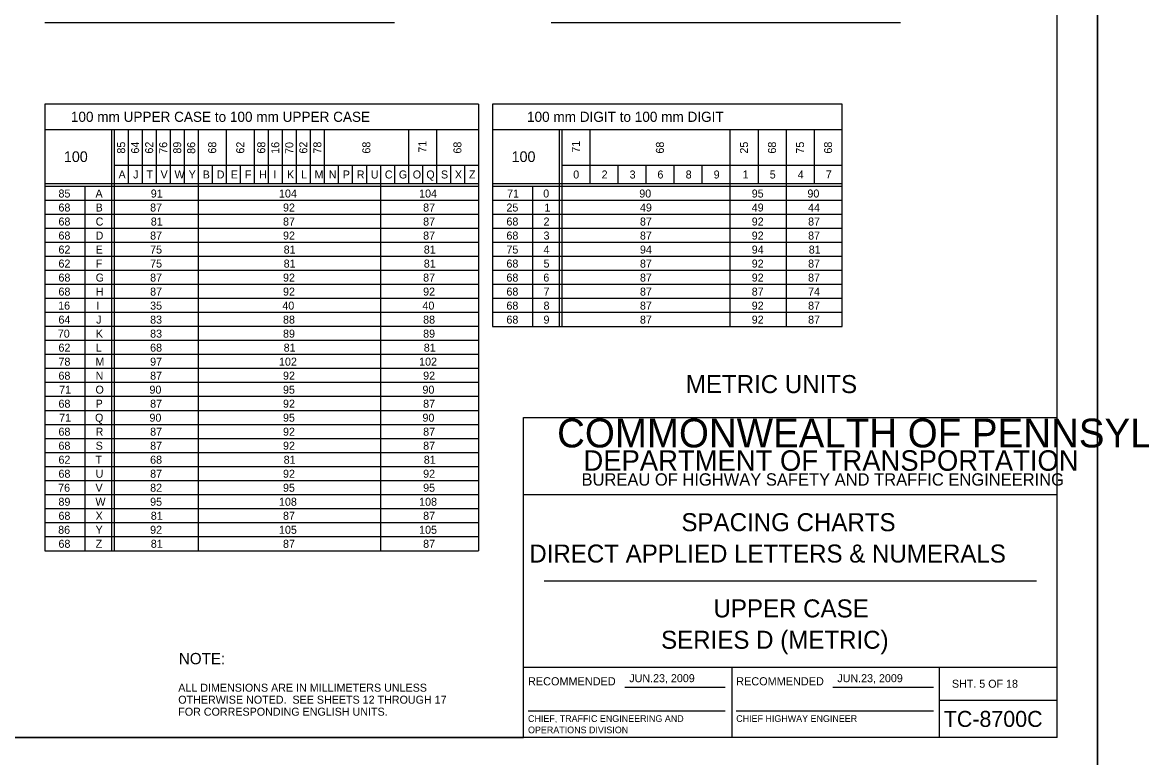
# Model space of a CAD drawing. Extents: x 637580 to 641849, y 297270 to 299646.
# Drawn here: x 638859.5 to 639278.9, y 299059.1 to 299334.6 of the extents above; entities that cross this region are included whole.
import ezdxf

# ---------------------------------------------------------------- set-up
doc = ezdxf.new("R2010")
doc.units = 0
for name, color, linetype in [('1', 7, 'Continuous'), ('2', 7, 'Continuous'), ('XCS-GRID-HVGL', 7, 'Continuous')]:
    doc.layers.add(name, color=color, linetype=linetype)

msp = doc.modelspace()

# ---------------------------------------------------------------- linework, layer by layer
at = {"layer": '1'}
for p, q in [((639247.31, 299066.63), (639247.31, 299630.63)), ((639047.31, 299066.63), (639047.31, 299186.63)), ((639047.31, 299186.63), (639247.31, 299186.63)), ((639247.31, 299157.63), (639047.31, 299157.63)), ((639055.06, 299125.31), (639239.56, 299125.31)), ((639047.31, 299093), (639247.31, 299093)), ((639125.31, 299093), (639125.31, 299066.63)), ((639203.19, 299066.63), (639203.19, 299093)), ((639085.24, 299085.57), (639122.87, 299085.57)), ((639163.24, 299085.57), (639200.87, 299085.57)), ((639048.99, 299076.68), (639122.87, 299076.68)), ((639126.99, 299076.68), (639200.87, 299076.68)), ((639203.19, 299080.63), (639247.31, 299080.63)), ((639247.31, 299066.63), (638461.31, 299066.63)), ((638461.31, 299066.63), (639047.31, 299066.63))]:
    msp.add_line(p, q, dxfattribs=at)
at = {"layer": '2'}
for p, q in [((638867.91, 299334.63), (638998.91, 299334.63)), ((639057.61, 299334.63), (639188.61, 299334.63)), ((639030.41, 299304), (638867.91, 299304)), ((638867.91, 299304), (638867.91, 299136.63)), ((639030.41, 299304), (639030.41, 299136.63)), ((639166.66, 299304), (639035.66, 299304)), ((639035.66, 299304), (639035.66, 299220.63)), ((639166.66, 299220.63), (639166.66, 299304)), ((638867.91, 299294.5), (639030.41, 299294.5)), ((638892.91, 299294.5), (638892.91, 299136.63)), ((638893.91, 299294.5), (638893.91, 299136.63)), ((638899.16, 299294.5), (638899.16, 299274.13)), ((638904.41, 299294.5), (638904.41, 299274.13)), ((638909.66, 299294.5), (638909.66, 299274.13)), ((638914.91, 299294.5), (638914.91, 299274.13)), ((638920.16, 299294.5), (638920.16, 299274.13)), ((638925.41, 299294.5), (638925.41, 299136.63)), ((638935.91, 299294.5), (638935.91, 299274.13)), ((638946.41, 299294.5), (638946.41, 299274.13)), ((638951.66, 299294.5), (638951.66, 299274.13)), ((638956.91, 299294.5), (638956.91, 299274.13)), ((638962.16, 299294.5), (638962.16, 299274.13)), ((638967.41, 299294.5), (638967.41, 299274.13)), ((638972.66, 299294.5), (638972.66, 299274.13)), ((639004.16, 299294.5), (639004.16, 299274.13)), ((639014.66, 299294.5), (639014.66, 299274.13)), ((639035.66, 299294.5), (639166.66, 299294.5)), ((639060.66, 299294.5), (639060.66, 299220.63)), ((639061.66, 299294.5), (639061.66, 299220.63)), ((639072.16, 299294.5), (639072.16, 299274.13)), ((639124.66, 299294.5), (639124.66, 299220.63)), ((639135.16, 299294.5), (639135.16, 299274.13)), ((639145.66, 299294.5), (639145.66, 299220.63)), ((639156.16, 299294.5), (639156.16, 299274.13)), ((638893.91, 299281.13), (639030.41, 299281.13)), ((638930.66, 299281.13), (638930.66, 299274.13)), ((638941.16, 299281.13), (638941.16, 299274.13)), ((638977.91, 299281.13), (638977.91, 299274.13)), ((638983.16, 299281.13), (638983.16, 299274.13)), ((638988.41, 299281.13), (638988.41, 299274.13)), ((638988.41, 299281.13), (638988.41, 299274.13)), ((638993.66, 299281.13), (638993.66, 299136.63)), ((638998.91, 299281.13), (638998.91, 299274.13)), ((639009.41, 299281.13), (639009.41, 299274.13)), ((639019.91, 299281.13), (639019.91, 299274.13)), ((639025.16, 299281.13), (639025.16, 299274.13)), ((639061.66, 299281.13), (639166.66, 299281.13)), ((639082.66, 299281.13), (639082.66, 299274.13)), ((639093.16, 299281.13), (639093.16, 299274.13)), ((639103.66, 299281.13), (639103.66, 299274.13)), ((639114.16, 299281.13), (639114.16, 299274.13)), ((639030.41, 299274.13), (638867.91, 299274.13)), ((639166.66, 299274.13), (639035.66, 299274.13)), ((639030.41, 299273.13), (638867.91, 299273.13)), ((638882.91, 299273.13), (638882.91, 299136.63)), ((639166.66, 299273.13), (639035.66, 299273.13)), ((639050.66, 299273.13), (639050.66, 299220.63)), ((639030.41, 299267.88), (638867.91, 299267.88)), ((639166.66, 299267.88), (639035.66, 299267.88)), ((639030.41, 299262.63), (638867.91, 299262.63)), ((639166.66, 299262.63), (639035.66, 299262.63)), ((639030.41, 299257.38), (638867.91, 299257.38)), ((639166.66, 299257.38), (639035.66, 299257.38)), ((639030.41, 299252.13), (638867.91, 299252.13)), ((639166.66, 299252.13), (639035.66, 299252.13)), ((639030.41, 299246.88), (638867.91, 299246.88)), ((639166.66, 299246.88), (639035.66, 299246.88)), ((639030.41, 299241.63), (638867.91, 299241.63)), ((639166.66, 299241.63), (639035.66, 299241.63)), ((639030.41, 299236.38), (638867.91, 299236.38)), ((639166.66, 299236.38), (639035.66, 299236.38)), ((639030.41, 299231.13), (638867.91, 299231.13)), ((639166.66, 299231.13), (639035.66, 299231.13)), ((639030.41, 299225.88), (638867.91, 299225.88)), ((639166.66, 299225.88), (639035.66, 299225.88)), ((639030.41, 299220.63), (638867.91, 299220.63)), ((639035.66, 299220.63), (639166.66, 299220.63)), ((639030.41, 299215.38), (638867.91, 299215.38)), ((639030.41, 299210.13), (638867.91, 299210.13)), ((639030.41, 299204.88), (638867.91, 299204.88)), ((639030.41, 299199.63), (638867.91, 299199.63)), ((639030.41, 299194.38), (638867.91, 299194.38)), ((639030.41, 299189.13), (638867.91, 299189.13)), ((639030.41, 299183.88), (638867.91, 299183.88)), ((639030.41, 299178.63), (638867.91, 299178.63)), ((639030.41, 299173.38), (638867.91, 299173.38)), ((639030.41, 299168.13), (638867.91, 299168.13)), ((639030.41, 299162.88), (638867.91, 299162.88)), ((639030.41, 299157.63), (638867.91, 299157.63)), ((639030.41, 299152.38), (638867.91, 299152.38)), ((639030.41, 299147.13), (638867.91, 299147.13)), ((639030.41, 299141.88), (638867.91, 299141.88)), ((638867.91, 299136.63), (638867.91, 299136.63)), ((638867.91, 299136.63), (639030.41, 299136.63))]:
    msp.add_line(p, q, dxfattribs=at)
at = {"layer": 'XCS-GRID-HVGL'}
for points in [[(638421.31, 299645.63), (639262.31, 299645.63), (639262.31, 299051.63), (638421.31, 299051.63)], [(639262.31, 299645.63), (640103.31, 299645.63), (640103.31, 299051.63), (639262.31, 299051.63)]]:
    msp.add_lwpolyline(points, close=True, dxfattribs=at)

# ---------------------------------------------------------------- texts
at = {"layer": '1'}
for s, height, p in [('COMMONWEALTH OF PENNSYLVANIA', 10.7828, (639059.9, 299175.36)), ('DEPARTMENT OF TRANSPORTATION', 7.6837, (639069.76, 299166.61)), ('BUREAU OF HIGHWAY SAFETY AND TRAFFIC ENGINEERING', 4.6253, (639069.04, 299161.04)), ('SPACING CHARTS', 6.75, (639106.47, 299143.97)), ('DIRECT APPLIED LETTERS & NUMERALS', 6.75, (639049.47, 299132.22)), ('UPPER CASE', 6.75, (639118.47, 299111.66)), ('SERIES D (METRIC)', 6.75, (639098.84, 299099.91)), ('RECOMMENDED', 3.048, (639048.99, 299086.2)), ('RECOMMENDED', 3.048, (639126.99, 299086.2)), ('SHT. 5 OF 18', 3, (639207.82, 299085.31)), ('TC-8700C', 6, (639204.77, 299070.63)), ('CHIEF, TRAFFIC ENGINEERING AND', 2.5, (639048.99, 299072.51)), ('CHIEF HIGHWAY ENGINEER', 2.5, (639126.99, 299072.51)), ('OPERATIONS DIVISION', 2.5, (639048.99, 299068.26))]:
    msp.add_text(s, height=height, dxfattribs=at).set_placement(p)
at = {"layer": '2'}
for s, height, p in [('100 mm UPPER CASE to 100 mm UPPER CASE', 3.8, (638877.7, 299297.35)), ('100 mm DIGIT to 100 mm DIGIT', 3.8, (639048.61, 299297.35)), ('100', 4, (638875.1, 299282.31)), ('100', 4, (639042.85, 299282.31)), ('A', 3, (638895.56, 299276.13)), ('J', 3, (638901.04, 299276.13)), ('T', 3, (638906.04, 299276.13)), ('V', 3, (638911.31, 299276.13)), ('W', 3, (638916.53, 299276.13)), ('Y', 3, (638921.84, 299276.13)), ('B', 3, (638927.1, 299276.13)), ('D', 3, (638932.35, 299276.13)), ('E', 3, (638937.62, 299276.13)), ('F', 3, (638942.92, 299276.13)), ('H', 3, (638948.19, 299276.13)), ('I', 3, (638953.6, 299276.13)), ('K', 3, (638958.69, 299276.13)), ('L', 3, (638963.94, 299276.13)), ('M', 3, (638969.03, 299276.13)), ('N', 3, (638974.35, 299276.13)), ('P', 3, (638979.6, 299276.13)), ('R', 3, (638984.85, 299276.13)), ('U', 3, (638990.09, 299276.13)), ('C', 3, (638995.35, 299276.13)), ('G', 3, (639000.6, 299276.13)), ('O', 3, (639005.81, 299276.13)), ('Q', 3, (639010.88, 299276.13)), ('S', 3, (639016.37, 299276.13)), ('X', 3, (639021.59, 299276.13)), ('Z', 3, (639026.85, 299276.13)), ('0', 3, (639065.93, 299276.13)), ('2', 3, (639076.56, 299276.13)), ('3', 3, (639087.06, 299276.13)), ('6', 3, (639097.48, 299276.13)), ('8', 3, (639108.06, 299276.13)), ('9', 3, (639118.55, 299276.13)), ('1', 3, (639129.4, 299276.13)), ('5', 3, (639139.56, 299276.13)), ('4', 3, (639150.06, 299276.13)), ('7', 3, (639160.56, 299276.13)), ('85', 3, (638873.06, 299269)), ('A', 3, (638886.93, 299269)), ('91', 3, (638907.65, 299269)), ('104', 3, (638955.69, 299269)), ('104', 3, (639008.19, 299269)), ('71', 3, (639041.15, 299269)), ('0', 3, (639054.68, 299269)), ('90', 3, (639090.68, 299269)), ('95', 3, (639132.81, 299269)), ('90', 3, (639153.68, 299269)), ('68', 3, (638873.06, 299263.75)), ('B', 3, (638886.98, 299263.75)), ('87', 3, (638907.4, 299263.75)), ('92', 3, (638957.19, 299263.75)), ('87', 3, (639009.69, 299263.75)), ('25', 3, (639040.9, 299263.75)), ('1', 3, (639055.15, 299263.75)), ('49', 3, (639090.93, 299263.75)), ('49', 3, (639132.81, 299263.75)), ('44', 3, (639153.93, 299263.75)), ('68', 3, (638873.06, 299258.5)), ('C', 3, (638886.98, 299258.5)), ('81', 3, (638907.65, 299258.5)), ('87', 3, (638957.19, 299258.5)), ('87', 3, (639009.69, 299258.5)), ('68', 3, (639040.9, 299258.5)), ('2', 3, (639054.81, 299258.5)), ('87', 3, (639090.93, 299258.5)), ('92', 3, (639132.81, 299258.5)), ('87', 3, (639153.93, 299258.5)), ('68', 3, (638873.06, 299253.25)), ('D', 3, (638886.98, 299253.25)), ('87', 3, (638907.4, 299253.25)), ('92', 3, (638957.19, 299253.25)), ('87', 3, (639009.69, 299253.25)), ('68', 3, (639040.9, 299253.25)), ('3', 3, (639054.81, 299253.25)), ('87', 3, (639090.93, 299253.25)), ('92', 3, (639132.81, 299253.25)), ('87', 3, (639153.93, 299253.25)), ('62', 3, (638873.06, 299248)), ('E', 3, (638886.99, 299248)), ('75', 3, (638907.4, 299248)), ('81', 3, (638957.44, 299248)), ('81', 3, (639009.94, 299248)), ('75', 3, (639040.9, 299248)), ('4', 3, (639054.81, 299248)), ('94', 3, (639090.93, 299248)), ('94', 3, (639132.81, 299248)), ('81', 3, (639154.18, 299248)), ('62', 3, (638873.06, 299242.75)), ('F', 3, (638887.05, 299242.75)), ('75', 3, (638907.4, 299242.75)), ('81', 3, (638957.44, 299242.75)), ('81', 3, (639009.94, 299242.75)), ('68', 3, (639040.9, 299242.75)), ('5', 3, (639054.81, 299242.75)), ('87', 3, (639090.93, 299242.75)), ('92', 3, (639132.81, 299242.75)), ('87', 3, (639153.93, 299242.75)), ('68', 3, (638873.06, 299237.5)), ('G', 3, (638886.98, 299237.5)), ('87', 3, (638907.4, 299237.5)), ('92', 3, (638957.19, 299237.5)), ('87', 3, (639009.69, 299237.5)), ('68', 3, (639040.9, 299237.5)), ('6', 3, (639054.73, 299237.5)), ('87', 3, (639090.93, 299237.5)), ('92', 3, (639132.81, 299237.5)), ('87', 3, (639153.93, 299237.5)), ('68', 3, (638873.06, 299232.25)), ('H', 3, (638887.06, 299232.25)), ('87', 3, (638907.4, 299232.25)), ('92', 3, (638957.19, 299232.25)), ('92', 3, (639009.69, 299232.25)), ('68', 3, (639040.9, 299232.25)), ('7', 3, (639054.81, 299232.25)), ('87', 3, (639090.93, 299232.25)), ('87', 3, (639132.81, 299232.25)), ('74', 3, (639153.93, 299232.25)), ('16', 3, (638872.94, 299227)), ('I', 3, (638887.23, 299227)), ('35', 3, (638907.4, 299227)), ('40', 3, (638956.94, 299227)), ('40', 3, (639009.44, 299227)), ('68', 3, (639040.9, 299227)), ('8', 3, (639054.81, 299227)), ('87', 3, (639090.93, 299227)), ('92', 3, (639132.81, 299227)), ('87', 3, (639153.93, 299227)), ('64', 3, (638873.06, 299221.75)), ('J', 3, (638887.17, 299221.75)), ('83', 3, (638907.4, 299221.75)), ('88', 3, (638957.19, 299221.75)), ('88', 3, (639009.69, 299221.75)), ('68', 3, (639040.9, 299221.75)), ('9', 3, (639054.8, 299221.75)), ('87', 3, (639090.93, 299221.75)), ('92', 3, (639132.81, 299221.75)), ('87', 3, (639153.93, 299221.75)), ('70', 3, (638872.81, 299216.5)), ('K', 3, (638887.06, 299216.5)), ('83', 3, (638907.4, 299216.5)), ('89', 3, (638957.19, 299216.5)), ('89', 3, (639009.69, 299216.5)), ('62', 3, (638873.06, 299211.25)), ('L', 3, (638887.06, 299211.25)), ('68', 3, (638907.4, 299211.25)), ('81', 3, (638957.44, 299211.25)), ('81', 3, (639009.94, 299211.25)), ('78', 3, (638873.06, 299206)), ('M', 3, (638886.91, 299206)), ('97', 3, (638907.4, 299206)), ('102', 3, (638955.69, 299206)), ('102', 3, (639008.19, 299206)), ('68', 3, (638873.06, 299200.75)), ('N', 3, (638886.98, 299200.75)), ('87', 3, (638907.4, 299200.75)), ('92', 3, (638957.19, 299200.75)), ('92', 3, (639009.69, 299200.75)), ('METRIC UNITS', 6.75, (639108.11, 299195.72)), ('71', 3, (638873.31, 299195.5)), ('O', 3, (638886.93, 299195.5)), ('90', 3, (638907.15, 299195.5)), ('95', 3, (638957.19, 299195.5)), ('90', 3, (639009.44, 299195.5)), ('68', 3, (638873.06, 299190.25)), ('P', 3, (638886.98, 299190.25)), ('87', 3, (638907.4, 299190.25)), ('92', 3, (638957.19, 299190.25)), ('87', 3, (639009.69, 299190.25)), ('71', 3, (638873.31, 299185)), ('Q', 3, (638886.75, 299185)), ('90', 3, (638907.15, 299185)), ('95', 3, (638957.19, 299185)), ('90', 3, (639009.44, 299185)), ('68', 3, (638873.06, 299179.75)), ('R', 3, (638886.98, 299179.75)), ('87', 3, (638907.4, 299179.75)), ('92', 3, (638957.19, 299179.75)), ('87', 3, (639009.69, 299179.75)), ('68', 3, (638873.06, 299174.5)), ('S', 3, (638886.99, 299174.5)), ('87', 3, (638907.4, 299174.5)), ('92', 3, (638957.19, 299174.5)), ('87', 3, (639009.69, 299174.5)), ('62', 3, (638873.06, 299169.25)), ('T', 3, (638886.92, 299169.25)), ('68', 3, (638907.4, 299169.25)), ('81', 3, (638957.44, 299169.25)), ('81', 3, (639009.94, 299169.25)), ('68', 3, (638873.06, 299164)), ('U', 3, (638886.97, 299164)), ('87', 3, (638907.4, 299164)), ('92', 3, (638957.19, 299164)), ('92', 3, (639009.69, 299164)), ('76', 3, (638872.94, 299158.75)), ('V', 3, (638886.93, 299158.75)), ('82', 3, (638907.4, 299158.75)), ('95', 3, (638957.19, 299158.75)), ('95', 3, (639009.69, 299158.75)), ('89', 3, (638873.06, 299153.5)), ('W', 3, (638886.91, 299153.5)), ('95', 3, (638907.4, 299153.5)), ('108', 3, (638955.69, 299153.5)), ('108', 3, (639008.19, 299153.5)), ('68', 3, (638873.06, 299148.25)), ('X', 3, (638886.97, 299148.25)), ('81', 3, (638907.65, 299148.25)), ('87', 3, (638957.19, 299148.25)), ('87', 3, (639009.69, 299148.25)), ('86', 3, (638872.94, 299143)), ('Y', 3, (638886.97, 299143)), ('92', 3, (638907.4, 299143)), ('105', 3, (638955.69, 299143)), ('105', 3, (639008.19, 299143)), ('68', 3, (638873.06, 299137.75)), ('Z', 3, (638886.98, 299137.75)), ('81', 3, (638907.65, 299137.75)), ('87', 3, (638957.19, 299137.75)), ('87', 3, (639009.69, 299137.75)), ('NOTE:', 4.25, (638918.16, 299094.1)), ('JUN.23, 2009', 3, (639086.93, 299087.39)), ('ALL DIMENSIONS ARE IN MILLIMETERS UNLESS', 3, (638917.94, 299083.83)), ('OTHERWISE NOTED.  SEE SHEETS 12 THROUGH 17', 3, (638917.94, 299079.33)), ('FOR CORRESPONDING ENGLISH UNITS.', 3, (638917.94, 299074.83))]:
    msp.add_text(s, height=height, dxfattribs=at).set_placement(p)
for s, rotation, p in [('85', 90, (638898.04, 299285.46)), ('64', 90, (638903.29, 299285.46)), ('62', 90, (638908.54, 299285.46)), ('76', 90, (638913.79, 299285.38)), ('89', 90, (638919.04, 299285.45)), ('86', 90, (638924.29, 299285.38)), ('68', 90, (638932.16, 299285.46)), ('62', 90, (638942.66, 299285.46)), ('68', 90, (638950.54, 299285.46)), ('16', 90, (638955.79, 299285.38)), ('70', 90, (638961.04, 299285.33)), ('62', 90, (638966.29, 299285.46)), ('78', 90, (638971.54, 299285.46)), ('68', 90, (638989.91, 299285.46)), ('71', 90, (639010.91, 299285.81)), ('68', 90, (639024.04, 299285.46)), ('71', 90, (639068.41, 299285.81)), ('68', 90, (639099.91, 299285.46)), ('25', 90, (639131.41, 299285.46)), ('68', 90, (639141.91, 299285.46)), ('75', 90, (639152.41, 299285.46)), ('68', 90, (639162.91, 299285.46)), ('JUN.23, 2009', 360, (639164.88, 299087.39))]:
    msp.add_text(s, height=3, rotation=rotation, dxfattribs=at).set_placement(p)

doc.saveas('drawing.dxf')
